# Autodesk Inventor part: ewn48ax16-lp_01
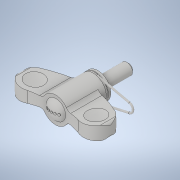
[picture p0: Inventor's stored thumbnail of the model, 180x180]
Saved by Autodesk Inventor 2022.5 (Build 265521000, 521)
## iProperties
Created: 2021-08
Part Number: ewn48ax16-lp_01
Material: 一般
Document SubType Name: Modeling
Designer: ImaoCorp
Density: 1 g/cm^3
Appearance: 既定
Author: ImaoCorp
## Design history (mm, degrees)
feature "ewn48ax16-lp_01"
node "ソリッド1"
